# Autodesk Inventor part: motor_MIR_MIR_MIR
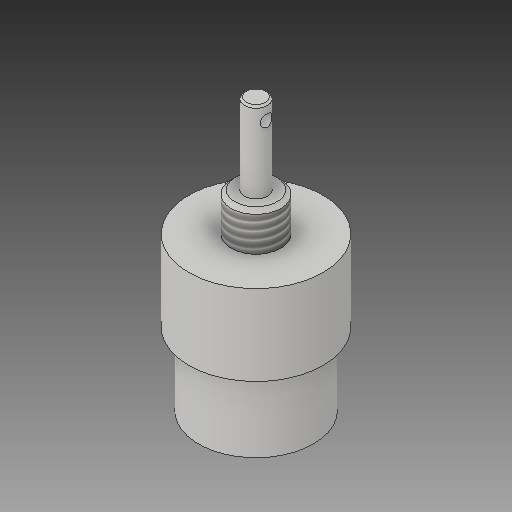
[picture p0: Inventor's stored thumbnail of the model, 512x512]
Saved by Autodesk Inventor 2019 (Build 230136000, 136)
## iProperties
Created: 2019-10
Part Number: motor_MIR_MIR_MIR
Material: Generic
Document SubType Name: Modeling
Designer: PRADYUMNA
Density: 1 g/cm^3
Appearance: Default
Author: Asus
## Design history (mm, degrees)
derived "motor_MIR_MIR.ipt"
  sketch "Sketch1"
    geometry: C1 r 6.5 at (0, 0) reference; 1 further point
  sketch "Sketch2"
    geometry: 1 further point
  sketch "Sketch3"
    geometry: C1 r 17.5 at (0, 0) reference; 1 further point
  sketch "Sketch4"
    geometry: C1 r 15 at (0, 0) reference; 1 further point
  sketch "Sketch5"
    geometry: C1 r 3 at (0, 0) reference; 1 further point
  sketch "Sketch6"
    geometry: C1 r 1.55 at (-27.143, 0) reference; 1 further point
  sketch "Sketch7"
    geometry: L1 (-12.192, 2.12)-(-11.485, 2.12) reference; L2 (-11.485, 2.12)-(-11.485, -2.356) reference; L3 (-11.485, -2.356)-(-12.192, -2.356) reference; L4 (-12.192, -2.356)-(-12.192, 2.12) reference; L5 (11.603, 2.12)-(12.546, 2.12) reference; L6 (12.546, 2.12)-(12.546, -2.356) reference; L7 (12.546, -2.356)-(11.603, -2.356) reference; L8 (11.603, -2.356)-(11.603, 2.12) reference; 1 further point
feature "Solid1::motor_MIR_MIR.ipt"
tag "TaggingFeature1"
body "Solid1"
